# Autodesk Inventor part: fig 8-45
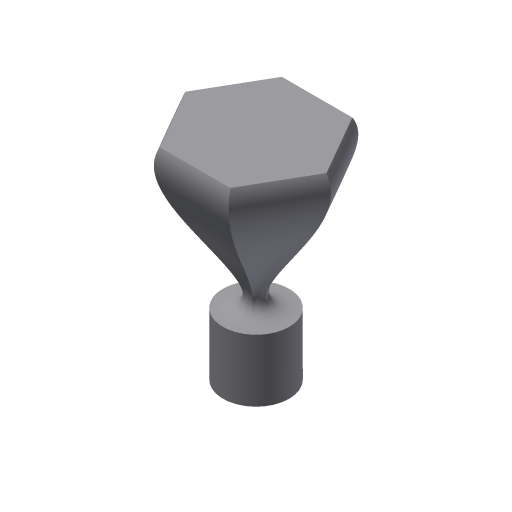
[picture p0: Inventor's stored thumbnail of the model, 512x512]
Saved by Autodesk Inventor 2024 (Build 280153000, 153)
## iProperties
Created: 2004-05
Part Number: fig 8-45
Document SubType Name: Modeling
Designer: CADCIM Technologies
Manufacturer: Standard
Standards Organization: Custom
Density: 1 g/cm^3
Material: Generic
Appearance: Default
Author: CADCIM Technologies
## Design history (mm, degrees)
sketch "Sketch1"
  geometry: C1 r 16.344 at (0, 0)
  constraints: 1 centre point
extrude "Extrusion1" new body sketch "Sketch1" distance "d0" = 30.75; taper "d1" = 0 deg
workplane "Work Plane1"
sketch "Sketch2"
  geometry: L1 (34.788, 0)-(17.394, -30.128); L2 (17.394, -30.128)-(-17.394, -30.128); L3 (-17.394, -30.128)-(-34.788, 0); L4 (-34.788, 0)-(-17.394, 30.128); L5 (-17.394, 30.128)-(17.394, 30.128); L6 (17.394, 30.128)-(34.788, 0); 2 further points
  constraints: 12 end point, 1 coincident, 12 other
loft "Loft2" sketch "Sketch2" dims "d9" = 15, "d10" = 90 deg, "d11" = 80, "d12" = 120 deg
  node "Edges2"
body "Solid1"
other parameters: "d2" = 75
